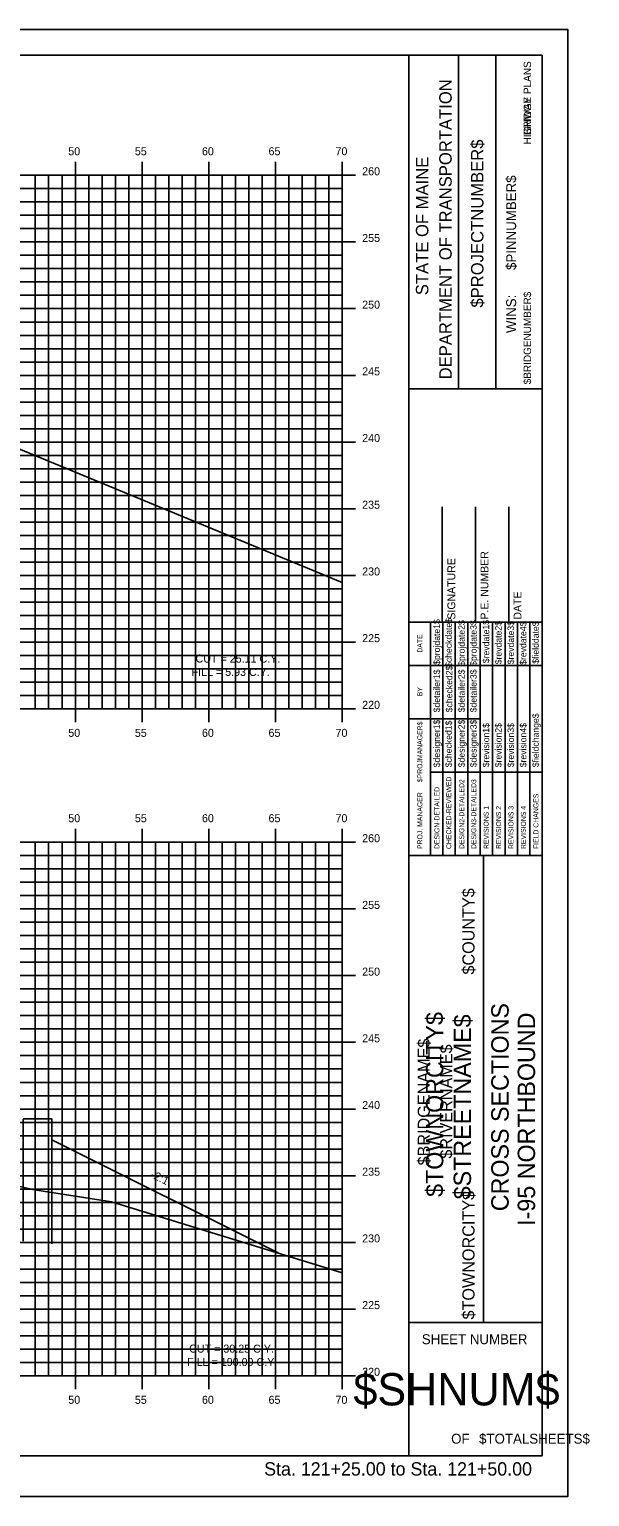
# Model space of a CAD drawing. Extents: x -22 to 1480, y -1511 to 8.
# Drawn here: x 1121.7 to 1163.7, y -1511.4 to -1401.4 of the extents above; entities that cross this region are included whole.
import ezdxf

# ---------------------------------------------------------------- set-up
doc = ezdxf.new("R2010")
doc.units = 0
for name, color, linetype in [('ANNOTATION', 7, 'Continuous'), ('BORDER', 7, 'Continuous'), ('BRIDGE_TITLE', 7, 'Continuous'), ('D_Bridge_Wingwall', 7, 'Continuous'), ('D_Roadway_SlopeLines', 7, 'Continuous'), ('H_V ANNOTATION', 7, 'Continuous'), ('HIGHWAY_TITLE', 7, 'Continuous'), ('MAJOR', 7, 'Continuous'), ('MINOR', 7, 'Continuous'), ('PLOT BOUNDARY', 7, 'Continuous'), ('S_Roadway_Centerline', 7, 'Continuous')]:
    doc.layers.add(name, color=color, linetype=linetype)

msp = doc.modelspace()

# ---------------------------------------------------------------- linework, layer by layer
at = {"layer": 'BORDER'}
for p, q in [((1160.18, -1403.33), (1000.18, -1403.33)), ((1150.18, -1508.33), (1150.18, -1403.33)), ((1153.91, -1428.33), (1153.91, -1403.33)), ((1156.71, -1428.33), (1156.71, -1403.33)), ((1160.18, -1508.33), (1160.18, -1403.33)), ((1150.18, -1428.34), (1160.18, -1428.34)), ((1152.68, -1445.83), (1152.68, -1437.18)), ((1155.18, -1445.83), (1155.18, -1437.18)), ((1157.68, -1445.83), (1157.68, -1437.18)), ((1150.18, -1445.83), (1160.18, -1445.83)), ((1150.18, -1463.33), (1160.18, -1463.33)), ((1155.77, -1498.33), (1155.77, -1463.33)), ((1150.18, -1498.33), (1160.18, -1498.33)), ((1000.18, -1508.33), (1160.18, -1508.33))]:
    msp.add_line(p, q, dxfattribs=at)
for points in [[(1151.8, -1449.08), (1151.8, -1445.83)], [(1152.73, -1463.33), (1152.73, -1445.83)], [(1153.66, -1445.83), (1153.66, -1463.33)], [(1154.59, -1463.33), (1154.59, -1445.83)], [(1155.53, -1463.33), (1155.53, -1445.83)], [(1156.46, -1463.33), (1156.46, -1445.83)], [(1157.39, -1463.33), (1157.39, -1445.83)], [(1158.32, -1463.33), (1158.32, -1445.83)], [(1159.25, -1463.33), (1159.25, -1445.83)], [(1151.8, -1463.33), (1151.8, -1446.53)], [(1150.18, -1449.08), (1160.18, -1449.08)], [(1150.18, -1453.08), (1151.8, -1453.08)], [(1151.8, -1453.08), (1155.52, -1453.08)], [(1151.8, -1457.08), (1160.18, -1457.08)]]:
    msp.add_lwpolyline(points, dxfattribs=at)
at = {"layer": 'D_Bridge_Wingwall'}
msp.add_lwpolyline([(1121.28, -1492.23), (1121.28, -1483.07), (1123.42, -1483.07), (1123.42, -1483.07), (1123.42, -1492.44)], dxfattribs=at)
at = {"layer": 'D_Roadway_SlopeLines'}
msp.add_line((1123.42, -1484.64), (1140.38, -1493.12), dxfattribs=at)
at = {"layer": 'MAJOR'}
for p, q in [((1005.18, -1412.33), (1145.18, -1412.33)), ((1005.18, -1412.33), (1145.18, -1412.33)), ((1125.18, -1411.33), (1125.18, -1412.33)), ((1125.18, -1452.33), (1125.18, -1412.33)), ((1130.18, -1411.33), (1130.18, -1412.33)), ((1130.18, -1452.33), (1130.18, -1412.33)), ((1135.18, -1411.33), (1135.18, -1412.33)), ((1135.18, -1452.33), (1135.18, -1412.33)), ((1140.18, -1411.33), (1140.18, -1412.33)), ((1140.18, -1452.33), (1140.18, -1412.33)), ((1146.18, -1412.33), (1144.18, -1412.33)), ((1145.18, -1411.33), (1145.18, -1412.33)), ((1145.18, -1452.33), (1145.18, -1412.33)), ((1145.18, -1452.33), (1145.18, -1412.33)), ((1005.18, -1417.33), (1145.18, -1417.33)), ((1146.18, -1417.33), (1144.18, -1417.33)), ((1005.18, -1422.33), (1145.18, -1422.33)), ((1146.18, -1422.33), (1144.18, -1422.33)), ((1005.18, -1427.33), (1145.18, -1427.33)), ((1146.18, -1427.33), (1144.18, -1427.33)), ((1005.18, -1432.33), (1145.18, -1432.33)), ((1146.18, -1432.33), (1144.18, -1432.33)), ((1005.18, -1437.33), (1145.18, -1437.33)), ((1146.18, -1437.33), (1144.18, -1437.33)), ((1005.18, -1442.33), (1145.18, -1442.33)), ((1146.18, -1442.33), (1144.18, -1442.33)), ((1005.18, -1447.33), (1145.18, -1447.33)), ((1146.18, -1447.33), (1144.18, -1447.33)), ((1005.18, -1452.33), (1145.18, -1452.33)), ((1005.18, -1452.33), (1145.18, -1452.33)), ((1125.18, -1453.33), (1125.18, -1452.33)), ((1130.18, -1453.33), (1130.18, -1452.33)), ((1135.18, -1453.33), (1135.18, -1452.33)), ((1140.18, -1453.33), (1140.18, -1452.33)), ((1146.18, -1452.33), (1144.18, -1452.33)), ((1145.18, -1453.33), (1145.18, -1452.33)), ((1125.18, -1461.33), (1125.18, -1462.33)), ((1130.18, -1461.33), (1130.18, -1462.33)), ((1135.18, -1461.33), (1135.18, -1462.33)), ((1140.18, -1461.33), (1140.18, -1462.33)), ((1145.18, -1461.33), (1145.18, -1462.33)), ((1005.18, -1462.33), (1145.18, -1462.33)), ((1005.18, -1462.33), (1145.18, -1462.33)), ((1125.18, -1502.33), (1125.18, -1462.33)), ((1130.18, -1502.33), (1130.18, -1462.33)), ((1135.18, -1502.33), (1135.18, -1462.33)), ((1140.18, -1502.33), (1140.18, -1462.33)), ((1146.18, -1462.33), (1144.18, -1462.33)), ((1145.18, -1502.33), (1145.18, -1462.33)), ((1145.18, -1502.33), (1145.18, -1462.33)), ((1005.18, -1467.33), (1145.18, -1467.33)), ((1146.18, -1467.33), (1144.18, -1467.33)), ((1005.18, -1472.33), (1145.18, -1472.33)), ((1146.18, -1472.33), (1144.18, -1472.33)), ((1005.18, -1477.33), (1145.18, -1477.33)), ((1146.18, -1477.33), (1144.18, -1477.33)), ((1005.18, -1482.33), (1145.18, -1482.33)), ((1146.18, -1482.33), (1144.18, -1482.33)), ((1005.18, -1487.33), (1145.18, -1487.33)), ((1146.18, -1487.33), (1144.18, -1487.33)), ((1005.18, -1492.33), (1145.18, -1492.33)), ((1146.18, -1492.33), (1144.18, -1492.33)), ((1005.18, -1497.33), (1145.18, -1497.33)), ((1146.18, -1497.33), (1144.18, -1497.33)), ((1005.18, -1502.33), (1145.18, -1502.33)), ((1005.18, -1502.33), (1145.18, -1502.33)), ((1125.18, -1503.33), (1125.18, -1502.33)), ((1130.18, -1503.33), (1130.18, -1502.33)), ((1135.18, -1503.33), (1135.18, -1502.33)), ((1140.18, -1503.33), (1140.18, -1502.33)), ((1146.18, -1502.33), (1144.18, -1502.33)), ((1145.18, -1503.33), (1145.18, -1502.33))]:
    msp.add_line(p, q, dxfattribs=at)
at = {"layer": 'MINOR'}
for p, q in [((1122.18, -1452.33), (1122.18, -1412.33)), ((1123.18, -1452.33), (1123.18, -1412.33)), ((1124.18, -1452.33), (1124.18, -1412.33)), ((1126.18, -1452.33), (1126.18, -1412.33)), ((1127.18, -1452.33), (1127.18, -1412.33)), ((1128.18, -1452.33), (1128.18, -1412.33)), ((1129.18, -1452.33), (1129.18, -1412.33)), ((1131.18, -1452.33), (1131.18, -1412.33)), ((1132.18, -1452.33), (1132.18, -1412.33)), ((1133.18, -1452.33), (1133.18, -1412.33)), ((1134.18, -1452.33), (1134.18, -1412.33)), ((1136.18, -1452.33), (1136.18, -1412.33)), ((1137.18, -1452.33), (1137.18, -1412.33)), ((1138.18, -1452.33), (1138.18, -1412.33)), ((1139.18, -1452.33), (1139.18, -1412.33)), ((1141.18, -1452.33), (1141.18, -1412.33)), ((1142.18, -1452.33), (1142.18, -1412.33)), ((1143.18, -1452.33), (1143.18, -1412.33)), ((1144.18, -1452.33), (1144.18, -1412.33)), ((1005.18, -1413.33), (1145.18, -1413.33)), ((1145.18, -1413.33), (1144.18, -1413.33)), ((1005.18, -1414.33), (1145.18, -1414.33)), ((1145.18, -1414.33), (1144.18, -1414.33)), ((1005.18, -1415.33), (1145.18, -1415.33)), ((1145.18, -1415.33), (1144.18, -1415.33)), ((1005.18, -1416.33), (1145.18, -1416.33)), ((1145.18, -1416.33), (1144.18, -1416.33)), ((1005.18, -1418.33), (1145.18, -1418.33)), ((1145.18, -1418.33), (1144.18, -1418.33)), ((1005.18, -1419.33), (1145.18, -1419.33)), ((1145.18, -1419.33), (1144.18, -1419.33)), ((1005.18, -1420.33), (1145.18, -1420.33)), ((1145.18, -1420.33), (1144.18, -1420.33)), ((1005.18, -1421.33), (1145.18, -1421.33)), ((1145.18, -1421.33), (1144.18, -1421.33)), ((1005.18, -1423.33), (1145.18, -1423.33)), ((1145.18, -1423.33), (1144.18, -1423.33)), ((1005.18, -1424.33), (1145.18, -1424.33)), ((1145.18, -1424.33), (1144.18, -1424.33)), ((1005.18, -1425.33), (1145.18, -1425.33)), ((1145.18, -1425.33), (1144.18, -1425.33)), ((1005.18, -1426.33), (1145.18, -1426.33)), ((1145.18, -1426.33), (1144.18, -1426.33)), ((1005.18, -1428.33), (1145.18, -1428.33)), ((1145.18, -1428.33), (1144.18, -1428.33)), ((1005.18, -1429.33), (1145.18, -1429.33)), ((1145.18, -1429.33), (1144.18, -1429.33)), ((1005.18, -1430.33), (1145.18, -1430.33)), ((1145.18, -1430.33), (1144.18, -1430.33)), ((1005.18, -1431.33), (1145.18, -1431.33)), ((1145.18, -1431.33), (1144.18, -1431.33)), ((1005.18, -1433.33), (1145.18, -1433.33)), ((1005.18, -1434.33), (1145.18, -1434.33)), ((1145.18, -1433.33), (1144.18, -1433.33)), ((1145.18, -1434.33), (1144.18, -1434.33)), ((1005.18, -1435.33), (1145.18, -1435.33)), ((1145.18, -1435.33), (1144.18, -1435.33)), ((1005.18, -1436.33), (1145.18, -1436.33)), ((1145.18, -1436.33), (1144.18, -1436.33)), ((1005.18, -1438.33), (1145.18, -1438.33)), ((1145.18, -1438.33), (1144.18, -1438.33)), ((1005.18, -1439.33), (1145.18, -1439.33)), ((1145.18, -1439.33), (1144.18, -1439.33)), ((1005.18, -1440.33), (1145.18, -1440.33)), ((1145.18, -1440.33), (1144.18, -1440.33)), ((1005.18, -1441.33), (1145.18, -1441.33)), ((1145.18, -1441.33), (1144.18, -1441.33)), ((1005.18, -1443.33), (1145.18, -1443.33)), ((1145.18, -1443.33), (1144.18, -1443.33)), ((1005.18, -1444.33), (1145.18, -1444.33)), ((1005.18, -1445.33), (1145.18, -1445.33)), ((1145.18, -1444.33), (1144.18, -1444.33)), ((1145.18, -1445.33), (1144.18, -1445.33)), ((1005.18, -1446.33), (1145.18, -1446.33)), ((1145.18, -1446.33), (1144.18, -1446.33)), ((1005.18, -1448.33), (1145.18, -1448.33)), ((1145.18, -1448.33), (1144.18, -1448.33)), ((1005.18, -1449.33), (1145.18, -1449.33)), ((1145.18, -1449.33), (1144.18, -1449.33)), ((1005.18, -1450.33), (1145.18, -1450.33)), ((1145.18, -1450.33), (1144.18, -1450.33)), ((1005.18, -1451.33), (1145.18, -1451.33)), ((1145.18, -1451.33), (1144.18, -1451.33)), ((1122.18, -1502.33), (1122.18, -1462.33)), ((1123.18, -1502.33), (1123.18, -1462.33)), ((1124.18, -1502.33), (1124.18, -1462.33)), ((1126.18, -1502.33), (1126.18, -1462.33)), ((1127.18, -1502.33), (1127.18, -1462.33)), ((1128.18, -1502.33), (1128.18, -1462.33)), ((1129.18, -1502.33), (1129.18, -1462.33)), ((1131.18, -1502.33), (1131.18, -1462.33)), ((1132.18, -1502.33), (1132.18, -1462.33)), ((1133.18, -1502.33), (1133.18, -1462.33)), ((1134.18, -1502.33), (1134.18, -1462.33)), ((1136.18, -1502.33), (1136.18, -1462.33)), ((1137.18, -1502.33), (1137.18, -1462.33)), ((1138.18, -1502.33), (1138.18, -1462.33)), ((1139.18, -1502.33), (1139.18, -1462.33)), ((1141.18, -1502.33), (1141.18, -1462.33)), ((1142.18, -1502.33), (1142.18, -1462.33)), ((1143.18, -1502.33), (1143.18, -1462.33)), ((1144.18, -1502.33), (1144.18, -1462.33)), ((1005.18, -1463.33), (1145.18, -1463.33)), ((1145.18, -1463.33), (1144.18, -1463.33)), ((1005.18, -1464.33), (1145.18, -1464.33)), ((1145.18, -1464.33), (1144.18, -1464.33)), ((1005.18, -1465.33), (1145.18, -1465.33)), ((1145.18, -1465.33), (1144.18, -1465.33)), ((1005.18, -1466.33), (1145.18, -1466.33)), ((1145.18, -1466.33), (1144.18, -1466.33)), ((1005.18, -1468.33), (1145.18, -1468.33)), ((1145.18, -1468.33), (1144.18, -1468.33)), ((1005.18, -1469.33), (1145.18, -1469.33)), ((1145.18, -1469.33), (1144.18, -1469.33)), ((1005.18, -1470.33), (1145.18, -1470.33)), ((1145.18, -1470.33), (1144.18, -1470.33)), ((1005.18, -1471.33), (1145.18, -1471.33)), ((1145.18, -1471.33), (1144.18, -1471.33)), ((1005.18, -1473.33), (1145.18, -1473.33)), ((1145.18, -1473.33), (1144.18, -1473.33)), ((1005.18, -1474.33), (1145.18, -1474.33)), ((1145.18, -1474.33), (1144.18, -1474.33)), ((1005.18, -1475.33), (1145.18, -1475.33)), ((1145.18, -1475.33), (1144.18, -1475.33)), ((1005.18, -1476.33), (1145.18, -1476.33)), ((1145.18, -1476.33), (1144.18, -1476.33)), ((1005.18, -1478.33), (1145.18, -1478.33)), ((1145.18, -1478.33), (1144.18, -1478.33)), ((1005.18, -1479.33), (1145.18, -1479.33)), ((1145.18, -1479.33), (1144.18, -1479.33)), ((1005.18, -1480.33), (1145.18, -1480.33)), ((1145.18, -1480.33), (1144.18, -1480.33)), ((1005.18, -1481.33), (1145.18, -1481.33)), ((1145.18, -1481.33), (1144.18, -1481.33)), ((1005.18, -1483.33), (1145.18, -1483.33)), ((1145.18, -1483.33), (1144.18, -1483.33)), ((1005.18, -1484.33), (1145.18, -1484.33)), ((1145.18, -1484.33), (1144.18, -1484.33)), ((1005.18, -1485.33), (1145.18, -1485.33)), ((1145.18, -1485.33), (1144.18, -1485.33)), ((1005.18, -1486.33), (1145.18, -1486.33)), ((1145.18, -1486.33), (1144.18, -1486.33)), ((1005.18, -1488.33), (1145.18, -1488.33)), ((1005.18, -1489.33), (1145.18, -1489.33)), ((1145.18, -1488.33), (1144.18, -1488.33)), ((1145.18, -1489.33), (1144.18, -1489.33)), ((1005.18, -1490.33), (1145.18, -1490.33)), ((1145.18, -1490.33), (1144.18, -1490.33)), ((1005.18, -1491.33), (1145.18, -1491.33)), ((1145.18, -1491.33), (1144.18, -1491.33)), ((1005.18, -1493.33), (1145.18, -1493.33)), ((1145.18, -1493.33), (1144.18, -1493.33)), ((1005.18, -1494.33), (1145.18, -1494.33)), ((1145.18, -1494.33), (1144.18, -1494.33)), ((1005.18, -1495.33), (1145.18, -1495.33)), ((1145.18, -1495.33), (1144.18, -1495.33)), ((1005.18, -1496.33), (1145.18, -1496.33)), ((1145.18, -1496.33), (1144.18, -1496.33)), ((1005.18, -1498.33), (1145.18, -1498.33)), ((1145.18, -1498.33), (1144.18, -1498.33)), ((1005.18, -1499.33), (1145.18, -1499.33)), ((1005.18, -1500.33), (1145.18, -1500.33)), ((1145.18, -1499.33), (1144.18, -1499.33)), ((1145.18, -1500.33), (1144.18, -1500.33)), ((1005.18, -1501.33), (1145.18, -1501.33)), ((1145.18, -1501.33), (1144.18, -1501.33))]:
    msp.add_line(p, q, dxfattribs=at)
at = {"layer": 'PLOT BOUNDARY'}
msp.add_lwpolyline([(992.09, -1511.39), (1162.09, -1511.39), (1162.09, -1401.39), (992.09, -1401.39)], close=True, dxfattribs=at)
at = {"layer": 'S_Roadway_Centerline'}
for points in [[(1116.57, -1431.03), (1145.18, -1442.87)], [(1101.21, -1483.38), (1121.96, -1488.36), (1127.89, -1489.29), (1145.18, -1494.6)], [(1101.21, -1483.38), (1121.96, -1488.36), (1127.89, -1489.29), (1145.18, -1494.6)]]:
    msp.add_lwpolyline(points, dxfattribs=at)

# ---------------------------------------------------------------- texts
at = {"layer": 'ANNOTATION'}
for s, rotation, p in [('CUT = 25.11 C.Y.', 359.9241, (1134.19, -1448.86)), ('FILL = 5.93 C.Y.', 359.9241, (1133.89, -1449.86)), ('-2:1', 333.4349, (1130.77, -1487.43)), ('CUT = 30.25 C.Y.', 359.9241, (1133.71, -1500.59)), ('FILL = 190.09 C.Y.', 359.9241, (1133.56, -1501.59))]:
    msp.add_text(s, height=0.6, rotation=rotation, dxfattribs=at).set_placement(p)
at = {"layer": 'BORDER'}
for s, height, rotation, p in [('DEPARTMENT OF TRANSPORTATION', 0.9318, 90, (1153.39, -1427.63)), ('$PROJECTNUMBER$', 0.9318, 90, (1155.77, -1422.25)), ('STATE OF MAINE', 0.9318, 90, (1151.64, -1421.32)), ('$PINNUMBER$', 0.7453, 90, (1158.22, -1419.43)), ('WINS:', 0.745, 90, (1158.22, -1424.16)), ('P.E. NUMBER', 0.5906, 90, (1156.14, -1445.64)), ('SIGNATURE', 0.591, 90, (1153.66, -1445.64)), ('DATE', 0.591, 90, (1158.62, -1445.64)), ('$projdate1$', 0.4845, 90, (1152.51, -1449.03)), ('$checkdate$', 0.4845, 90, (1153.4, -1449.19)), ('$projdate2$', 0.4845, 90, (1154.37, -1449.11)), ('$projdate3$', 0.4845, 90, (1155.26, -1449.11)), ('$revdate1$', 0.485, 90, (1156.2, -1448.91)), ('$revdate2$', 0.485, 90, (1157.13, -1448.99)), ('$revdate3$', 0.485, 90, (1158.06, -1448.99)), ('$revdate4$', 0.485, 90, (1158.99, -1449.03)), ('$fielddate$', 0.4845, 90, (1159.92, -1448.95)), ('DATE', 0.371, 90, (1151.19, -1448.12)), ('$detailer1$', 0.4845, 90, (1152.51, -1452.59)), ('$checked2$', 0.485, 90, (1153.44, -1452.59)), ('$detailer2$', 0.4845, 90, (1154.37, -1452.59)), ('$detailer3$', 0.4845, 90, (1155.26, -1452.59)), ('BY', 0.371, 90, (1151.19, -1451.39)), ('$fieldchange$', 0.4845, 90, (1159.92, -1456.71)), ('$PROJMANAGER$', 0.3727, 90, (1151.19, -1457.83)), ('$designer1$', 0.4845, 90, (1152.51, -1456.71)), ('$checked1$', 0.485, 90, (1153.4, -1456.71)), ('$designer2$', 0.4845, 90, (1154.37, -1456.71)), ('$designer3$', 0.4845, 90, (1155.26, -1456.71)), ('$revision1$', 0.4845, 90, (1156.2, -1456.71)), ('$revision2$', 0.4845, 90, (1157.13, -1456.71)), ('$revision3$', 0.4845, 90, (1158.06, -1456.71)), ('$revision4$', 0.4845, 90, (1158.99, -1456.71)), ('DESIGN-DETAILED', 0.3727, 90, (1152.47, -1462.84)), ('CHECKED-REVIEWED', 0.3727, 90, (1153.36, -1462.84)), ('DESIGN2-DETAILED2', 0.3727, 90, (1154.33, -1462.84)), ('DESIGN3-DETAILED3', 0.3727, 90, (1155.23, -1462.84)), ('PROJ. MANAGER', 0.3727, 90, (1151.19, -1462.84)), ('FIELD CHANGES', 0.3727, 90, (1159.89, -1462.84)), ('REVISIONS 1', 0.3727, 90, (1156.16, -1462.84)), ('REVISIONS 2', 0.3727, 90, (1157.09, -1462.84)), ('REVISIONS 3', 0.3727, 90, (1158.02, -1462.84)), ('REVISIONS 4', 0.3727, 90, (1158.95, -1462.84)), ('CROSS SECTIONS', 1.3043, 90, (1157.66, -1489.99)), ('I-95 NORTHBOUND', 1.3043, 90, (1159.64, -1491.09)), ('SHEET NUMBER', 0.7453, 360, (1151.15, -1499.96)), ('$SHNUM$', 2.419, 360, (1146.02, -1504.55)), ('OF', 0.745, 360, (1153.35, -1507.42)), ('$TOTALSHEETS$', 0.7453, 360, (1155.44, -1507.42))]:
    msp.add_text(s, height=height, rotation=rotation, dxfattribs=at).set_placement(p)
at = {"layer": 'BRIDGE_TITLE'}
for s, height, p in [('BRIDGE PLANS', 0.559, (1159.34, -1409.31)), ('$BRIDGENUMBER$', 0.559, (1159.34, -1428)), ('$COUNTY$', 0.907, (1155.1, -1472.25)), ('$BRIDGENAME$', 0.9072, (1151.75, -1486.56)), ('$RIVERNAME$', 0.9072, (1153.43, -1486.05)), ('$TOWNORCITY$', 0.9072, (1155.1, -1498.11))]:
    msp.add_text(s, height=height, rotation=90, dxfattribs=at).set_placement(p)
at = {"layer": 'H_V ANNOTATION'}
for s, height, p in [('50', 0.6, (1124.65, -1410.83)), ('55', 0.6, (1129.64, -1410.83)), ('60', 0.6, (1134.67, -1410.83)), ('65', 0.6, (1139.66, -1410.83)), ('70', 0.6, (1144.68, -1410.83)), ('260', 0.6, (1146.68, -1412.33)), ('255', 0.6, (1146.68, -1417.33)), ('250', 0.6, (1146.68, -1422.33)), ('245', 0.6, (1146.68, -1427.33)), ('240', 0.6, (1146.68, -1432.33)), ('235', 0.6, (1146.68, -1437.33)), ('230', 0.6, (1146.68, -1442.33)), ('225', 0.6, (1146.68, -1447.33)), ('220', 0.6, (1146.68, -1452.33)), ('50', 0.6, (1124.65, -1454.43)), ('55', 0.6, (1129.64, -1454.43)), ('60', 0.6, (1134.67, -1454.43)), ('65', 0.6, (1139.66, -1454.43)), ('70', 0.6, (1144.68, -1454.43)), ('50', 0.6, (1124.65, -1460.83)), ('55', 0.6, (1129.64, -1460.83)), ('60', 0.6, (1134.67, -1460.83)), ('65', 0.6, (1139.66, -1460.83)), ('70', 0.6, (1144.68, -1460.83)), ('260', 0.6, (1146.68, -1462.33)), ('255', 0.6, (1146.68, -1467.33)), ('250', 0.6, (1146.68, -1472.33)), ('245', 0.6, (1146.68, -1477.33)), ('240', 0.6, (1146.68, -1482.33)), ('235', 0.6, (1146.68, -1487.33)), ('230', 0.6, (1146.68, -1492.33)), ('225', 0.6, (1146.68, -1497.33)), ('220', 0.6, (1146.68, -1502.33)), ('50', 0.6, (1124.65, -1504.43)), ('55', 0.6, (1129.64, -1504.43)), ('60', 0.6, (1134.67, -1504.43)), ('65', 0.6, (1139.66, -1504.43)), ('70', 0.6, (1144.68, -1504.43)), ('Sta. 121+25.00 to Sta. 121+50.00', 1.0002, (1139.33, -1509.81))]:
    msp.add_text(s, height=height, dxfattribs=at).set_placement(p)
at = {"layer": 'HIGHWAY_TITLE'}
for s, height, p in [('HIGHWAY PLANS', 0.559, (1159.34, -1410.02)), ('$TOWNORCITY$', 1.3043, (1152.76, -1488.92)), ('$STREETNAME$', 1.3043, (1154.84, -1489.1))]:
    msp.add_text(s, height=height, rotation=90, dxfattribs=at).set_placement(p)

doc.saveas('drawing.dxf')
